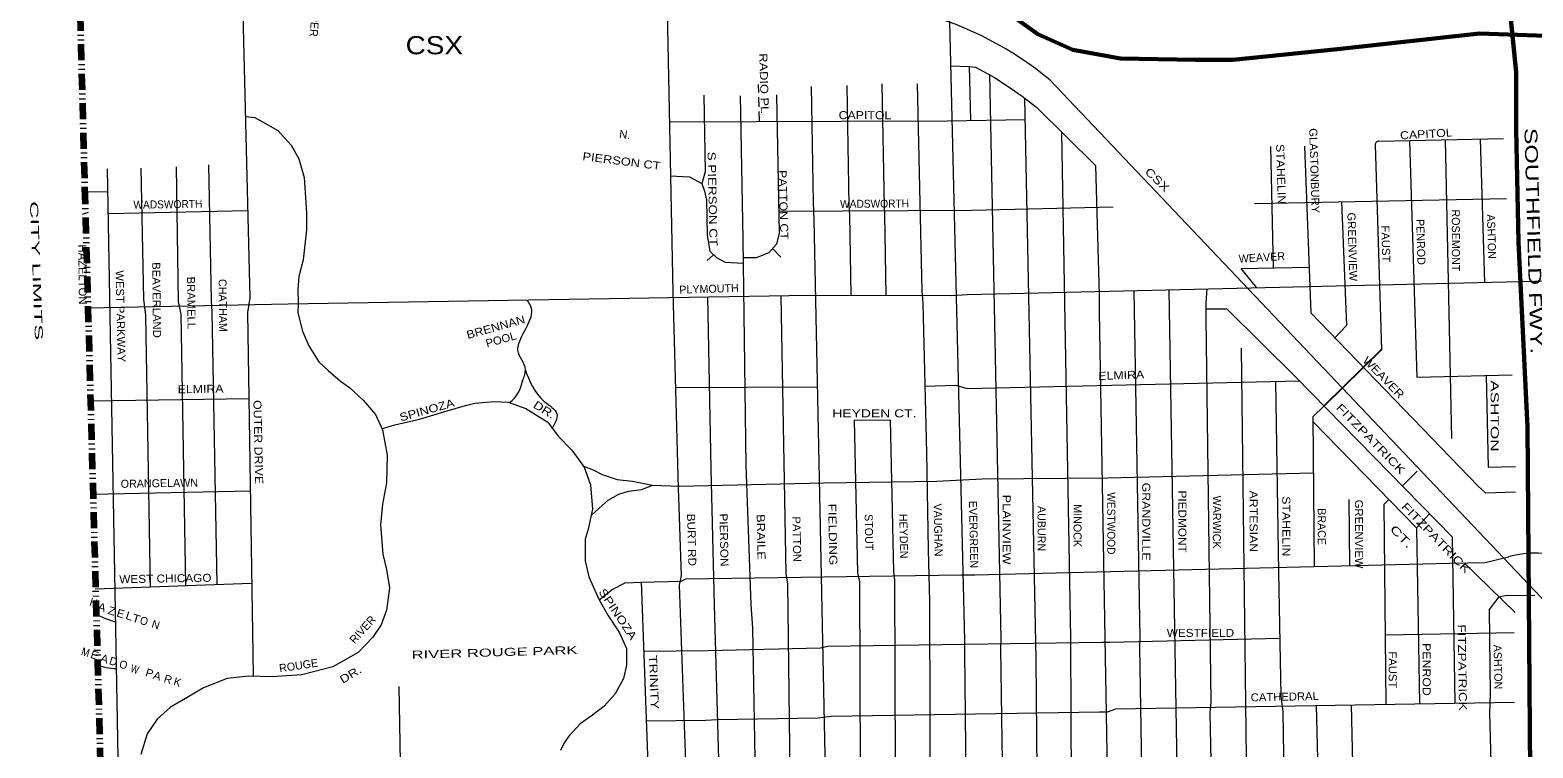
# Model space of a CAD drawing. Extents: x 34705 to 138605, y 34275 to 143551.
# Drawn here: x 40071 to 54154, y 110508 to 117233 of the extents above; entities that cross this region are included whole.
import ezdxf
from ezdxf.enums import TextEntityAlignment as Align

# ---------------------------------------------------------------- set-up
doc = ezdxf.new("R2010")
doc.units = 0
doc.header["$LTSCALE"] = 30
doc.linetypes.add('DASH_DOUBLE_DOT', pattern=[9.2, 5, -1.2, 0.3, -1.2, 0.3, -1.2])
doc.linetypes.add('MEDIUM_DASHED', pattern=[4.5, 3, -1.5])
for name, color, linetype, lineweight in [('1', 7, 'Continuous', 13), ('11', 7, 'Continuous', 13), ('50', 7, 'Continuous', 13), ('51', 7, 'Continuous', 35), ('59', 7, 'DASH_DOUBLE_DOT', 106)]:
    doc.layers.add(name, color=color, linetype=linetype, lineweight=lineweight)

msp = doc.modelspace()

# ---------------------------------------------------------------- linework, layer by layer
at = {"layer": '1'}
for p, q in [((48871.54, 116893.33), (48884.13, 116386.94)), ((49390, 116592.06), (49495.56, 111338.04)), ((52709.97, 116192.55), (53876.92, 116215.71)), ((52997.8, 116196.21), (53067.18, 113980.04)), ((53330.95, 116203.87), (53390.94, 113407.5)), ((53659.31, 116210.99), (53699.85, 114868.41)), ((51693.51, 116140.69), (51720.85, 115005.47)), ((52675.04, 116158.52), (52733.33, 114238.84)), ((40583.86, 115717.11), (40799.14, 115719.9)), ((51542.99, 115607.78), (53905.36, 115653.8)), ((40802.8, 115515.55), (42111.08, 115541.99)), ((46474.32, 115126.39), (46415.08, 115074.49)), ((47031.22, 115184.93), (47107.49, 115106.35)), ((53067.18, 113980.04), (53959.78, 114003.44)), ((46125.15, 113883.47), (47447.19, 113892.06)), ((40637.15, 113759.84), (42120.77, 113781.77)), ((53069.32, 113099.7), (52929.56, 112961.38)), ((40652.51, 112885.4), (42133.98, 112915.49)), ((52428.91, 112836.11), (52433.4, 112215.36)), ((53062.01, 112570.23), (53185.41, 112699.55)), ((53509.28, 112240.38), (53985.75, 111776.45)), ((53705.93, 112243.67), (53925.39, 112297.56)), ((40680.47, 111998.47), (42147.13, 112052.34)), ((52768.99, 111567.24), (53977.93, 111590.4)), ((43527.1, 111084.78), (43554.8, 109415.6))]:
    msp.add_line(p, q, dxfattribs=at)
at = {"layer": '1', "linetype": 'MEDIUM_DASHED'}
msp.add_line((46906.88, 116379.03), (46897.41, 116722.76), dxfattribs=at)
at = {"layer": '1', "lineweight": 25}
msp.add_line((52733.16, 114238.99), (52196.89, 113712.47), dxfattribs=at)
at = {"layer": '1'}
for points in [[(47981.66, 141004.05), (48033.09, 139024.1), (48053.24, 138456.35), (48093.94, 137313.03), (48126.32, 135471.37), (48232.15, 132077.43), (48314.67, 129978.44), (48365.06, 128404.34), (48465.85, 125680.25), (48556.56, 122467.79), (48576.72, 121326.61), (48594.36, 121253.51), (48682.55, 117502.92), (48684.81, 117442.73), (48828.7, 111512.8), (48828.7, 111406.94), (48844.83, 109618.16), (48844.83, 109449.36), (48894.21, 107747.71), (49053.86, 101630.72)], [(45708.73, 130421.87), (45752.05, 128822.02), (45779.53, 127829.03), (45809.3, 126868.11), (45855.09, 125488.57), (45930.02, 122529.28), (45928.37, 122521.05), (45974.11, 120368.19), (46007.17, 119356.56), (46029.22, 118187.81), (46034.73, 117531.78), (46040.24, 117410.49), (46095.35, 114780.79), (46144.95, 112940.83), (46171.13, 112122.16), (46154.6, 112033.95), (46242.78, 109496.61), (46215.22, 109441.48), (46231.75, 108873.64), (46297.89, 106844.86)], [(42047.89, 118562.68), (42066.53, 117381.33), (42130.91, 114723.24), (42108.52, 114586.03), (42160.35, 111184.95)], [(48698.02, 116898.34), (48873.58, 116893.02), (48930.05, 116884.33), (49003.9, 116845.22), (49108.15, 116788.73), (49255.84, 116693.14), (49368.78, 116614.92), (49503.44, 116506.29), (50054.98, 115963.2)], [(49060.02, 116819.89), (49166.34, 111525.4), (49163.82, 111432.14), (49211.7, 108248.05), (49317.53, 104327.94), (49340.21, 104219.56), (49420.52, 100326.82)], [(46385.92, 116623.33), (46397.22, 115905.13), (46365.16, 115795.18), (46390.35, 115724.17), (46410.96, 115639.41), (46415.54, 115311.85), (46441.18, 115161.22), (46504.85, 115102.26), (46584.99, 115058.74), (46752.98, 115049.89)], [(46725.18, 116616.45), (46749.87, 115275.2), (46779.17, 113157.05), (46825.43, 111852.42), (46841.46, 111629.66), (46862.07, 110404.17), (46882.68, 108900.94), (46935.35, 106900.07), (46988.02, 106819.9), (47033.81, 105588.68), (47084.19, 105533.7), (47200.98, 105018.31), (47265.09, 104749.74), (47366.74, 104608.37)], [(47066.68, 116625.3), (47084.19, 115646.29), (47091.06, 115331.32), (47065.87, 115225.96), (46992.6, 115145.78), (46873.52, 115099.97), (46752.29, 115099.97)], [(47389.56, 116703.18), (47409.36, 115618.8), (47413.94, 115457.31), (47484.92, 112115.84), (47590.26, 106927.56), (47615.45, 106845.09), (47686.35, 104239.57)], [(47723.88, 116712.34), (47743.68, 115589.02), (47748.26, 115500.83), (47763.28, 114749.52)], [(48051.34, 116730.67), (48073.43, 115575.28), (48078.01, 115505.41), (48091.13, 114748.46)], [(48384.7, 116729.71), (48404.16, 115756.42), (48426.07, 114787.3), (48437.52, 114675.06), (48469.58, 113273.19), (48487.9, 112363.23), (48499.35, 111879.91), (48503.93, 109679.75), (48526.83, 108923.84), (48572.62, 107459.55), (48588.65, 106943.59), (48579.49, 106847.38), (48625.29, 105016.02), (48673.38, 103570.06), (48721.55, 101622.95)], [(42089.71, 116424.28), (42176.89, 116414.02), (42276.09, 116358.89), (42391.83, 116292.73), (42518.58, 116154.91), (42590.23, 116028.11), (42639.83, 115851.69), (42661.87, 115520.92), (42661.87, 115361.04), (42628.81, 115079.88), (42590.23, 114925.51), (42579.21, 114804.23), (42584.72, 114671.91), (42579.21, 114583.71), (42623.3, 114412.8), (42683.92, 114274.98), (42777.61, 114126.13), (42865.79, 114043.43), (42981.52, 113944.2), (43064.19, 113883.56), (43196.46, 113762.27), (43306.68, 113629.96), (43372.82, 113486.62), (43416.91, 113249.56), (43411.4, 112990.45), (43372.82, 112791.98), (43356.29, 112599.03), (43378.33, 112323.38), (43411.4, 112180.04), (43438.95, 112007.77), (43411.4, 111798.28), (43361.8, 111660.45), (43284.64, 111544.68), (43146.86, 111401.34), (42909.88, 111269.03), (42617.78, 111191.85), (42336.71, 111175.31), (42121.78, 111180.82), (41917.86, 111158.77), (41697.41, 111070.56), (41526.57, 110971.33), (41388.79, 110888.63), (41262.03, 110778.37), (41168.34, 110640.55), (41107.71, 110447.59)], [(46072.88, 116373.76), (47673.59, 116378.1), (48668.33, 116382.45), (49394.54, 116395.94)], [(49735.28, 116278), (49763.52, 114677.37), (49818.96, 111540.53), (49824, 110789.4), (49829.57, 109614.81), (49829.57, 109503.77), (49866.83, 108258.13), (49972.66, 104332.98), (49987.78, 104232.16), (50088.99, 99953.7)], [(52012.64, 116146.48), (52072.77, 114582.67), (53640.7, 112958.71), (53710.07, 112898.56), (53990.44, 112905.95)], [(40795.29, 115934.12), (40912.86, 109384.12), (41025.73, 109277.48), (41338.3, 104498.23)], [(41108.81, 115940.39), (41133.89, 114710.99), (41152.71, 114560.45), (41195.9, 112017.4)], [(41441.15, 115952.94), (41459.96, 114685.9), (41485.04, 114573), (41528.55, 112029.62)], [(41742.13, 115971.76), (41767.21, 114698.45), (41773.48, 114591.82), (41822.88, 112040.43)], [(50054.98, 115963.2), (50088.57, 114747.94), (50088.57, 114594.19), (50141.49, 111535.49), (50154.09, 110827.21), (50196.92, 108248.05), (50287.63, 104353.15), (50312.83, 104239.72), (50406.36, 100111.75)], [(46072.58, 115867.65), (46188.59, 115862.13), (46250.46, 115856.5), (46365.3, 115794.79)], [(52360.39, 115623.71), (52405.78, 114465.84), (52296.32, 114351.13)], [(47086.57, 115537.26), (48899.65, 115545.98), (50220.18, 115576.4)], [(40613.4, 114632.16), (42489.2, 114668.24), (47370.61, 114750.8), (48708.52, 114746.45), (48856.21, 114755.14), (56295.69, 114929.11), (59170.26, 114975.24), (60993.76, 115036.75), (61270.46, 115052.13), (62554.03, 115098.26), (64448.63, 115152.08), (64617.72, 115144.39), (66562.29, 115190.52), (67177.17, 115213.59), (67584.53, 115228.96), (71855.3, 115368.15)], [(51567.34, 114818.54), (51420.92, 114999.88), (52056.27, 115011.71)], [(50413.39, 114791.56), (50469.06, 111538.01), (50466.54, 111447.27), (50519.45, 108249.93), (50635.36, 104254.84), (50726.19, 100271.02)], [(50740.96, 114799.22), (50851.73, 108262.67), (50879.48, 106930.2), (50921.11, 105625.48), (51036.34, 100438.26)], [(51096.86, 114807.54), (51089.07, 114679.17), (51087.61, 114535.24), (51133.86, 110938.03), (51124.61, 110836.24), (51180.12, 108282.33), (51180.12, 108185.17), (51291.55, 104251.92), (51314.05, 102957.83), (51346.39, 101712.98), (51340.84, 101624.59), (51340.84, 101365.5), (51385.77, 99709.95)], [(46418, 114734.69), (46451.72, 113122.69), (46481.95, 111847.84), (46523.17, 110399.58), (46555.23, 108896.36), (46611.87, 106848.58)], [(47107.09, 114740.34), (47152.89, 112140.47), (47168.92, 112044.26), (47198.69, 109505.67), (47200.98, 109407.17), (47258.22, 106909.23), (47304.02, 106831.35), (47377.34, 104232.91)], [(51088.5, 114622.91), (51285.93, 114622.91), (51932.77, 113981.49), (53395.56, 112484.48), (53422.63, 110927.61)], [(51420.62, 114253.02), (51476.13, 109642.57), (51485.38, 109526.9), (51617.78, 104375.7), (51673.85, 101689.36), (51678.47, 101411.77), (51725.54, 99076.67)], [(48455.3, 113897.72), (48746.09, 113906.54), (48853.69, 113875.78), (51967.07, 113946.38)], [(51739.94, 113941.23), (51769.65, 112152.88), (51792.15, 110996.64), (51809.02, 110844.73), (51818.39, 110244.03), (51827.64, 110170.01), (52028.38, 101725.64), (52045.26, 101573.73), (52056.51, 101112.35), (52050.88, 101056.09), (52062.13, 100392.16), (52056.51, 100307.77), (52084.45, 99083.4)], [(53714.14, 113997), (53733.2, 113139.15), (53991.3, 113143.32)], [(43372.82, 113500.41), (43488.55, 113533.49), (43720.02, 113588.62), (43957.01, 113660.29), (44149.9, 113715.42), (44238.08, 113737.47), (44419.95, 113754.01), (44552.22, 113748.49), (44717.55, 113687.85), (44921.47, 113561.05), (45020.67, 113428.74), (45147.43, 113296.43), (45263.16, 113136.55), (45323.78, 112971.16), (45340.32, 112745.13), (45301.74, 112557.69), (45274.18, 112463.97), (45274.18, 112259.99), (45307.25, 112111.14), (45400.94, 111901.64), (45483.61, 111752.79), (45593.83, 111587.4), (45659.97, 111438.55), (45659.97, 111284.19), (45632.41, 111157.39), (45555.26, 111014.05), (45450.54, 110898.28), (45340.32, 110815.58), (45224.58, 110732.89), (45119.87, 110617.11), (45075.78, 110556.47), (45042.71, 110484.8)], [(52196.9, 113712.47), (52091.27, 113608.76), (52105.05, 112207.42)], [(47794.06, 113579.47), (48130.67, 113581.85), (48160.44, 112157.08), (48171.89, 112079.19), (48181.05, 109459.85), (48194.79, 109331.01), (48315.92, 104264.67)], [(47794.06, 113579.56), (47823.83, 112147.91), (47844.44, 112063.16), (47851.31, 109432.36), (48007, 104246.48)], [(52091.68, 113566.82), (53062, 112570.74), (53089.79, 110922.13)], [(45252.09, 113151.85), (45348.86, 113114.62), (45433.41, 113068.49), (45571.76, 113022.35), (45717.79, 113006.98), (45902.26, 112968.53), (46155.9, 112960.85), (47508.64, 112991.6), (48569.31, 113006.98), (48992.04, 113030.04), (50168.01, 113037.73), (52096.42, 113084.4)], [(45328.02, 112685.38), (45402.66, 112753.26), (45487.21, 112830.14), (45587.13, 112883.96), (45679.36, 112914.72), (45802.34, 112930.09), (45902.26, 112968.53)], [(52803.64, 112835.96), (52757.29, 112789.84), (52775.21, 110916.96)], [(45403.86, 111896.38), (45525.64, 111992.09), (45648.62, 112053.6), (45794.65, 112061.29), (46171.27, 112068.98), (46217.38, 112092.04), (48799.89, 112130.48), (48922.87, 112130.48), (53374.99, 112238.12), (53705.93, 112243.67)], [(45797.75, 112064.28), (45891.44, 109500.74), (45868.01, 109419.43), (45945.83, 106828.99)], [(53834.93, 111923.31), (53742.45, 111804.36), (53752.34, 111013.52), (53746.71, 110833.48), (53780.46, 109573.14), (53862.7, 106030.32), (53871.95, 105618.54), (54009.73, 100396.36)], [(53834.93, 111923.31), (53892.56, 111935.02), (54172.09, 111939.12)], [(40871.54, 111686.4), (40781.45, 111718.59), (40725.79, 111741.78), (40685.52, 111760.38)], [(45825.4, 111413.54), (46424.91, 111421.23), (47477.89, 111444.3), (47547.07, 111459.67), (50114.2, 111498.12), (50191.06, 111498.12), (51781.63, 111537.12)], [(49495.56, 111338.04), (49517.53, 108875.21), (49575.34, 106911.44), (49613.68, 105619.64), (49651.27, 104288.55)], [(45845.39, 110760.57), (46401.85, 110767.71), (46509.45, 110775.39), (47454.84, 110790.77), (47577.81, 110806.15), (50091.15, 110844.59), (50114.2, 110844.59), (50168.01, 110844.59), (50244.87, 110875.35), (53980.45, 110936.78)], [(52123.29, 110906.24), (52253.37, 105681.04), (52292.74, 104240.66), (52410.8, 99089.52)], [(52451.69, 110911.64), (52553.79, 106363.44), (52590.79, 105021.71), (52668.26, 101689.36), (52672.88, 101532.06), (52692.09, 100352.78), (52737.09, 99092.45)]]:
    msp.add_lwpolyline(points, dxfattribs=at)
for centre, radius, start, end in [((52708.32, 116159.46), 33.13, 87.14811, 181.61092), ((54168.04, 111463.65), 868.49, 68.96068, 106.22392), ((40884.05, 111718.51), 466.92, 245.92272, 269.35608)]:
    msp.add_arc(centre, radius, start, end, dxfattribs=at)
for points in [[(44682.22, 113935.63), (44713.04, 114046.58), (44713.11, 114050.7), (44642.03, 114233.63), (44651.36, 114295.4), (44760.76, 114652.73), (44728.62, 114702.84)], [(44709.06, 114054.9), (44889.5, 113754.45), (45007.12, 113636.78), (44959.22, 113493.1)]]:
    msp.add_spline(points, degree=3, dxfattribs=at)
at = {"layer": '11'}
msp.add_arc((44380.98, 113988.1), 305.93, 306.99913, 352.76142, dxfattribs=at)
at = {"layer": '50'}
msp.add_line((59512.68, 106348.96), (49626.02, 116766.15), dxfattribs=at)
msp.add_arc((47551.28, 114253.58), 3258.47, 50.45194, 74.44351, dxfattribs=at)
at = {"layer": '51', "lineweight": 60}
for points in [[(53247.59, 141475.55), (53367.81, 136119.69), (53437.19, 134090.91), (53460.32, 134053.9), (53501.94, 131503.46), (53659.2, 125572.1), (53705.45, 123295.79), (53737.83, 121494.87), (53784.08, 121152.5), (53816.45, 120138.11), (53862.7, 118347.6), (53920.69, 117583.67), (53996.83, 116839.32), (53996.26, 116300.14), (54017.35, 115245.27), (54103.21, 113517.38), (54126.34, 110285.67), (54140.21, 108707.98), (54144.84, 108035.97), (54101.7, 107394.41), (54140.21, 105981.73), (54195.72, 103679.98), (54256.6, 101226.04)], [(48854.63, 117669.11), (49514.91, 117195.42), (49843.37, 117046.99), (50290.23, 116966.93), (50990.53, 116953.58), (51340.96, 116954.17), (52322.56, 117053.7), (53651.68, 117200.44), (54278.61, 117180.42), (56361.16, 117273.82)]]:
    msp.add_lwpolyline(points, dxfattribs=at)
at = {"layer": '59'}
msp.add_lwpolyline([(40539.82, 117375.3), (40582.92, 115751.51), (40756.62, 109371.93)], dxfattribs=at)

# ---------------------------------------------------------------- texts
at = {"layer": '1', "width": 2.25}
msp.add_text('CITY LIMITS', height=75, rotation=272.106, dxfattribs=at).set_placement((40093.96, 114977.46), align=Align.CENTER)
at = {"layer": '11'}
for s, rotation, p in [('STEGNER', 265.21, (42709.94, 117414.33)), ('ROSEMONT', 270.099, (53393.77, 115262.47)), ('ASHTON', 271.677, (53728.35, 115297.17)), ('PENROD', 271.678, (53065.87, 115246.91)), ('WEAVER', 3.352, (51615.71, 115066.11)), ('CHATHAM', 270.699, (41840.52, 114652.87)), ('PLYMOUTH', 1.759, (46434.06, 114771.54)), ('ORANGELAWN', 0.962, (41283.51, 112950.45)), ('EVERGREEN', 271.19, (48875.36, 112506.56)), ('WARWICK', 270, (51154.39, 112623.13)), ('STOUT', 271.192, (47894.85, 112528.06)), ('HEYDEN', 271.19, (48220.32, 112491.33)), ('VAUGHAN', 271.191, (48543.32, 112549.11)), ('AUBURN', 270, (49511.99, 112563.11)), ('MINOCK', 270, (49848.8, 112589.99)), ('BRACE', 270.102, (52137.71, 112581.09)), ('N', 342.552, (41237.89, 111626.9)), ('RIVER', 48.043, (43215.33, 111591.85)), ('ASHTON', 271.272, (53788.9, 111265.33)), ('D', 342.552, (40840.61, 111282.69)), ('ROUGE', 8.454, (42592.76, 111243.27)), ('R', 342.552, (41353.06, 111115.61)), ('K', 342.552, (41441.07, 111089.56))]:
    msp.add_text(s, height=75, rotation=rotation, dxfattribs=at).set_placement(p, align=Align.CENTER)
for s, height, rotation, width, p in [('RADIO PL', 75, 271.646, 1.2, (46912.02, 116733.84)), ('CAPITOL', 75, 359.904, 1.15, (47894.53, 116398.29)), ('N.', 75, 352.745, 1.05, (45640.57, 116216.64)), ('GLASTONBURY', 75, 271.677, 1.05, (52068.68, 115914.6)), ('CAPITOL', 75, 3.354, 1.15, (53156.78, 116222.81)), ('SOUTHFIELD FWY.', 120, 271.584, 1.45, (54102.7, 115255.21)), ('PIERSON CT', 75, 352.745, 1.2, (45609, 115968.65)), ('S PIERSON CT', 75, 271.194, 1.25, (46429.14, 115650.3)), ('STAHELIN', 75, 271.678, 1.15, (51755.42, 115882.85)), ('PATTON CT', 75, 271.646, 1.15, (47093.39, 115593.5)), ('CSX', 75, 316, 1.3, (50607.62, 115804.35)), ('WADSWORTH', 75, 0.758, 0.95, (41363.23, 115563.56)), ('WADSWORTH', 75, 0.373, 0.95, (47984.52, 115569.06)), ('GREENVIEW', 75, 271.678, 1.05, (52424.33, 115201.33)), ('FAUST', 75, 271.677, 1.05, (52737.81, 115229.15)), ('HAZELTON', 75, 270.557, 1.05, (40526.03, 114942.74)), ('WEST PARKWAY', 75, 271.293, 1.05, (40882.41, 114550.77)), ('BEAVERLAND', 75, 270.7, 1.05, (41219.9, 114703.53)), ('BRAMELL', 75, 270.699, 1.05, (41544.72, 114677.35)), ('BRENNAN ', 75, 15.626, 1.15, (44460.42, 114418.84)), ('POOL', 75, 15.626, 1.05, (44494.09, 114298.46)), ('WEAVER', 75, 314.272, 1.15, (52727.02, 113952.68)), ('ELMIRA', 75, 2.069, 1.15, (50297.13, 113962.27)), ('ASHTON', 75, 270.099, 1.6, (53757.91, 113618)), ('ELMIRA', 75, 0.962, 1.15, (41670.06, 113833.44)), ('OUTER DRIVE', 75, 271.293, 1.15, (42172.49, 113371.3)), ('SPINOZA', 75, 15.626, 1.2, (43799.8, 113636.96)), ('DR.', 75, 328.126, 1.25, (44870.48, 113644.3)), ('HEYDEN CT. ', 75, 0.008, 1.3, (48001.04, 113604.97)), ('FITZPATRICK', 75, 314.299, 1.35, (52607.27, 113377.78)), ('GRANDVILLE', 75, 270, 1.15, (50492.57, 112627.34)), ('PLAINVIEW', 75, 270, 1.2, (49184.89, 112553.36)), ('WESTWOOD', 75, 270, 0.95, (50164.85, 112611.49)), ('PIEDMONT', 75, 270, 1.1, (50831.53, 112628.3)), ('ARTESIAN', 75, 270.099, 1.15, (51498.4, 112630.43)), ('STAHELIN', 75, 270.101, 1.15, (51805.62, 112583.9)), ('GREENVIEW', 75, 270.098, 1.05, (52486.45, 112511.29)), ('FITZPATRICK', 75, 314.114, 1.35, (53218.06, 112449.34)), ('BURT RD', 75, 271.479, 1.1, (46233.91, 112456.05)), ('PIERSON', 75, 271.191, 1.1, (46536.66, 112455.22)), ('BRAILE', 75, 271.188, 1.2, (46884.1, 112483.42)), ('PATTON', 75, 271.187, 1.05, (47218.8, 112462.37)), ('FIELDING', 75, 271.19, 1.25, (47555.55, 112506.14)), ('CT.', 75, 314.119, 1.55, (52894.4, 112461.88)), ('WEST CHICAGO', 75, 0.962, 1.1, (41339.97, 112057.75)), ('SPINOZA', 75, 303.68, 1.25, (45547.39, 111740.49)), ('H', 75, 342.552, 0.95, (40654.8, 111833.42)), ('A', 75, 342.552, 1.1, (40733.73, 111789.88)), ('Z', 75, 342.552, 1.15, (40826.15, 111755.56)), ('E', 75, 342.552, 1.05, (40909.29, 111730.95)), ('L', 75, 342.552, 1.2, (40990.56, 111708.29)), ('T', 75, 342.552, 1.2, (41054.69, 111684.09)), ('O', 75, 342.552, 0.95, (41128.35, 111661.58)), ('FITZPATRICK', 75, 270.996, 1.25, (53454.62, 111260.39)), ('M', 75, 342.552, 0.9, (40580.42, 111369.17)), ('E', 75, 342.552, 1.05, (40665.05, 111341.62)), ('RIVER ROUGE PARK', 75, 1.665, 1.55, (44424.28, 111365.81)), ('FAUST', 75, 270.1, 1.05, (52802.16, 111239.38)), ('PENROD ', 75, 270.1, 1.15, (53120.26, 111227)), ('A', 75, 342.552, 1.1, (40757.48, 111307.3)), ('O', 75, 342.552, 0.95, (40935.13, 111251.68)), ('W', 75, 342.552, 0.8, (41041.83, 111210.46)), ('P', 75, 342.552, 1.05, (41179.6, 111173.15)), ('DR.', 75, 31.503, 1.25, (43093.65, 111163.97)), ('TRINITY', 75, 272.093, 1.3, (45879.98, 111122.04)), ('A', 75, 342.552, 1.1, (41251.74, 111147.32)), ('CATHEDRAL', 75, 1.274, 1.05, (51828.91, 110950.28))]:
    msp.add_text(s, height=height, rotation=rotation, dxfattribs=dict(at, width=width)).set_placement(p, align=Align.CENTER)
at = {"layer": '11', "width": 1.1}
msp.add_text('WESTFIELD', height=75, dxfattribs=at).set_placement((51038.07, 111548.04), align=Align.CENTER)
at = {"layer": '50', "width": 1.15}
msp.add_text('CSX', height=170, dxfattribs=at).set_placement((43859.38, 117006.12), align=Align.CENTER)

doc.saveas('drawing.dxf')
